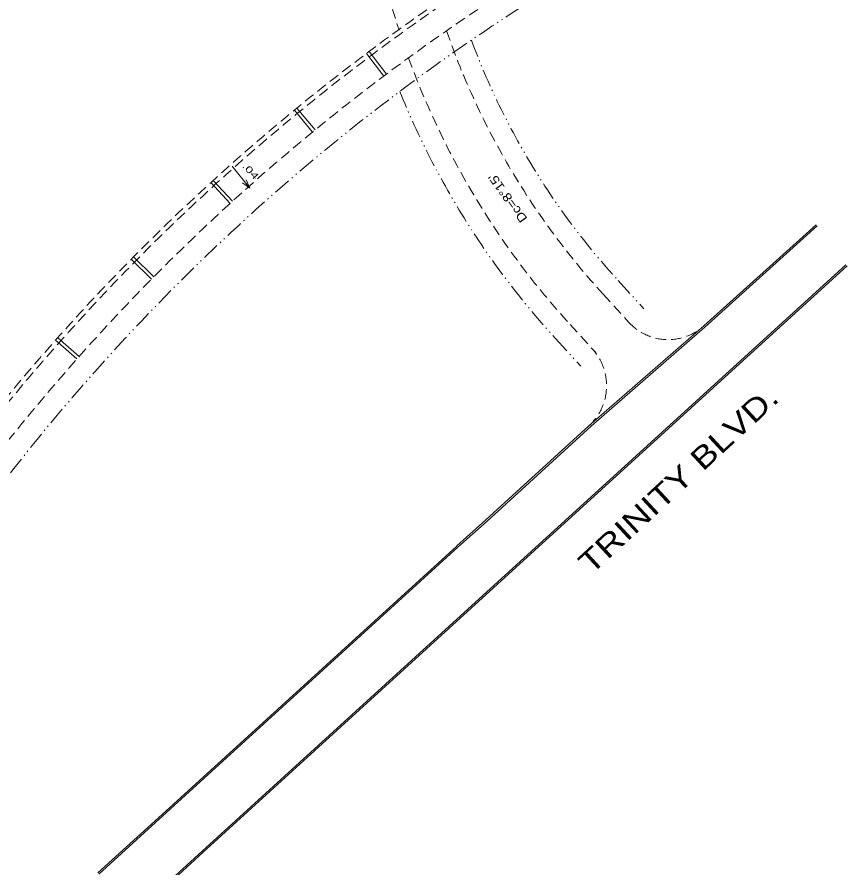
# Model space of a CAD drawing. Extents: x 2354993 to 2372084, y 6966390 to 6990057.
# Drawn here: x 2365387 to 2366146, y 6976742 to 6977519 of the extents above; entities that cross this region are included whole.
import ezdxf

# ---------------------------------------------------------------- set-up
doc = ezdxf.new("R2010")
doc.units = 0
doc.header["$LTSCALE"] = 3.2
doc.linetypes.add('DASH_DOUBLE_DOT', pattern=[9.2, 5, -1.2, 0.3, -1.2, 0.3, -1.2])
doc.linetypes.add('MEDIUM_DASHED', pattern=[4.5, 3, -1.5])
for name, color, linetype, lineweight in [('12', 7, 'Continuous', 13), ('15', 7, 'Continuous', 13), ('19', 7, 'Continuous', 13), ('5', 7, 'Continuous', 13), ('60', 7, 'DASH_DOUBLE_DOT', 13)]:
    doc.layers.add(name, color=color, linetype=linetype, lineweight=lineweight)

msp = doc.modelspace()

# ---------------------------------------------------------------- linework, layer by layer
at = {"layer": '12'}
for p, q in [((2365706.401, 6977485.815), (2365722.116, 6977465.102)), ((2365708.801, 6977487.615), (2365724.516, 6977466.902)), ((2365642.756, 6977435.874), (2365659.357, 6977415.864)), ((2365640.437, 6977433.972), (2365657.038, 6977413.96)), ((2365564.022, 6977367.745), (2365581.648, 6977348.63)), ((2365566.238, 6977369.767), (2365583.863, 6977350.651)), ((2365491.163, 6977297.58), (2365509.764, 6977279.414)), ((2365493.27, 6977299.715), (2365511.87, 6977281.548)), ((2365424.054, 6977225.908), (2365443.58, 6977208.74)), ((2365422.062, 6977223.666), (2365441.588, 6977206.498))]:
    msp.add_line(p, q, dxfattribs=at)
at = {"layer": '19'}
msp.add_line((2365599.587, 6977362.553), (2365592.852, 6977367.425), dxfattribs=at)
msp.add_lwpolyline([(2365583.635, 6977382.811), (2365599.587, 6977362.553), (2365596.433, 6977370.238)], dxfattribs=at)
at = {"layer": '5'}
for p, q in [((2366014.751, 6977236.761), (2366117.49, 6977329.187)), ((2366015.754, 6977235.646), (2366118.493, 6977328.072)), ((2365556.136, 6976756.497), (2366144.675, 6977292.612)), ((2365557.146, 6976755.388), (2366145.685, 6977291.503)), ((2365909.577, 6977145.178), (2366014.751, 6977236.761)), ((2365911.696, 6977145.082), (2366015.754, 6977235.646)), ((2365815.567, 6977059.288), (2365909.577, 6977145.178)), ((2365816.579, 6977058.181), (2365911.696, 6977145.082)), ((2365815.58, 6977059.3), (2365788.866, 6977035.463)), ((2365816.579, 6977058.181), (2365789.865, 6977034.344)), ((2365523.82, 6976791.997), (2365789.865, 6977034.344)), ((2365461.706, 6976735.455), (2365523.82, 6976791.997)), ((2365407.189, 6976620.909), (2365556.136, 6976756.497)), ((2365408.199, 6976619.8), (2365557.146, 6976755.388))]:
    msp.add_line(p, q, dxfattribs=at)
at = {"layer": '5', "linetype": 'MEDIUM_DASHED'}
for p, q in [((2365922.738, 6977265.696), (2365946.284, 6977239.915)), ((2365892.463, 6977238.046), (2365916.009, 6977212.265))]:
    msp.add_line(p, q, dxfattribs=at)
at = {"layer": '5'}
msp.add_lwpolyline([(2365460.696, 6976736.564), (2365522.81, 6976793.106), (2365788.855, 6977035.453)], dxfattribs=at)
at = {"layer": '5', "linetype": 'MEDIUM_DASHED'}
for centre, radius, start, end in [((2366864.416, 6975944.503), 1927.859, 114.19653, 168.16581), ((2366864.416, 6975944.503), 1923.859, 114.19652, 168.16581), ((2366864.416, 6975944.503), 1901.859, 114.19652, 168.16581), ((2366434.455, 6977733.014), 733.994, 186.19583, 197.93267), ((2366434.455, 6977733.014), 692.994, 199.07293, 222.40345), ((2366434.455, 6977733.014), 733.994, 200.00964, 222.40345), ((2365982.096, 6977272.621), 48.5, 222.40417, 312.31108), ((2365875.852, 6977182.092), 50, 312.41557, 42.40327)]:
    msp.add_arc(centre, radius, start, end, dxfattribs=at)
at = {"layer": '60'}
for p, q in [((2365936.398, 6977278.172), (2365959.944, 6977252.391)), ((2365878.803, 6977225.57), (2365902.349, 6977199.789))]:
    msp.add_line(p, q, dxfattribs=at)
for centre, radius, start, end in [((2366864.416, 6975944.503), 1881.859, 114.65077, 155.69784), ((2366434.455, 6977733.014), 674.494, 200.396, 222.40345), ((2366434.455, 6977733.014), 752.494, 202.00282, 222.40345)]:
    msp.add_arc(centre, radius, start, end, dxfattribs=at)

# ---------------------------------------------------------------- texts
at = {"layer": '15', "width": 1.25}
msp.add_text('TRINITY BLVD.', height=20, rotation=42.787, dxfattribs=at).set_placement((2365911.739, 6977008.548))
at = {"layer": '19'}
for s, height, rotation, width, p in [('.04', 6, 313.815, 1.55, (2365592.215, 6977382.374)), ("Dc=8°15'", 8, 125.518, 1.2, (2365853.851, 6977334.737))]:
    msp.add_text(s, height=height, rotation=rotation, dxfattribs=dict(at, width=width)).set_placement(p)

doc.saveas('drawing.dxf')
